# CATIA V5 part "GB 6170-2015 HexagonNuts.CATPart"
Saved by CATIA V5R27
Part number: GB 6170-2015 1型六角螺母
Bounding box of the stored display mesh (mm): x -1.848 to 1.848, y -1.6 to 1.6, z 0 to 1.3
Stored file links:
  E:\资料\Catia超级副本\GB 6170-2015 1型六角螺母\GB 6170-2015 HexagonNuts.CATPart
  E:\资料\Catia超级副本\GB 6170-2015 1型六角螺母\DesignTable1.xlsx
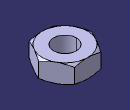
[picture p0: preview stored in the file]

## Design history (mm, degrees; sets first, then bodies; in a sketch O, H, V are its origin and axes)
Parameters
  s = 3.2 mm {design table}
  m = 1.3 mm {design table}
  `公称直径D` = 1.6 mm {design table}
AxisSystem1: origin (0, 0, 0), X (1, 0, 0), Y (0, 1, 0), Z (0, 0, 1)
Set1 "Inputs"
  Plane1: type Normal, Curve Line1, RefPoint Point1, Ratio 0
  Point1: (0, 0, 0), in AxisSystem1
Body1 (main body)
  Sketch1 on Plane1, origin (0, 0, 0), H (1, 0, 0), V (0, 1, 0)
    point P1 (0, 1.6)
    construction circle A1 centre (0, 0) radius 1.8475
    construction circle A2 centre (0, 0) radius 1.6
    point P2 (0.9238, 1.6)
    point P3 (-0.9238, 1.6)
    point P4 (-1.8475, 0)
    point P5 (-0.9238, -1.6)
    point P6 (0.9238, -1.6)
    point P7 (1.8475, 0)
    line L1 (0.9238, 1.6) -> (-0.9238, 1.6)
    line L2 (-0.9238, 1.6) -> (-1.8475, 0)
    line L3 (-1.8475, 0) -> (-0.9238, -1.6)
    line L4 (-0.9238, -1.6) -> (0.9238, -1.6)
    line L5 (0.9238, -1.6) -> (1.8475, 0)
    line L6 (1.8475, 0) -> (0.9238, 1.6)
    construction line L7 (0, 0) -> (0, 1.6)
    circle A3 centre (0, 0) radius 0.8
    radius A3 = 0.8 {= `公称直径D` /2}
    distance L1 L4 = 3.2 {= s}
    coincidence: A1 P2, A1 P3, A1 P4, A1 P5, A1 P6, A1 P7
    tangency: A2 L1, A2 L2, A2 L3, A2 L4, A2 L5, A2 L6
    midpoint: P1 L1
    vertical: L7 V
  Pad1: profile Sketch1, direction (0, 0, 1), length 1.3 {= m}
  Set2
    Line1: type PtDir, RefPoint Point1, Direction (0, 0, 1), Start 0, End 20
    Sketch2 on Plane2, origin (0, 0, 0), H (0, 1, 0), V (0, 0, 1)
      line L1 (-1.6, 1.3) -> (-2.3794, 0.85)
      point P1 (-1.6, 1.3)
      point P2 (-2.3794, 0.85)
      reference intersected line E1 through (0, 1.3) direction (-1, 0) from end face of Pad1
      line L2 (-1.6, 1.3) -> (-2.3794, 1.3)
      point P3 (-2.3794, 1.3)
      line L3 (-2.3794, 1.3) -> (-2.3794, 0.85)
      reference intersected line E2 through (0, 1.3) direction (-1, 0) from end face of Pad1
      reference intersected line E3 (-1.6, 0) -> (-1.6, 1.3) from face of Pad1 from Sketch1.L4
      construction line L4 (1.8007, 0.65) -> (-1.9077, 0.65)
      reference projected line E4 (0, 1.3) -> (-1.6, 1.3) from edge [face of Pad1 from Sketch1.L3 | end face of Pad1]
      reference projected line E5 (0, 0) -> (-1.6, 0) from edge [start face of Pad1 | face of Pad1 from Sketch1.L3]
      point P6 (-2.3794, 0)
      point P7 (-1.6, 0)
      line L5 (-1.6, 0) -> (-2.3794, 0)
      point P8 (-2.3794, 0.45)
      line L6 (-1.6, 0) -> (-2.3794, 0.45)
      line L7 (-2.3794, 0) -> (-2.3794, 0.45)
      angle L1 E1 = 30
      length L3 = 0.45 {= m /2-0.2mm}
      horizontal: L2 H, L4 H
      vertical: L3 V
      coincidence: L2 E2, P1 E3
      symmetry: E4 E5 L4, P3 P6 L4, P1 P7 L4, L2 L5 L4, P2 P8 L4, L1 L6 L4, L3 L7 L4
    Line2: type PtDir, RefPoint Point1, Direction (0, 1, 0), Start 0, End 20
    Plane2: type 2Lines, Element1 Line1, Element2 Line2
  Groove1: profile Sketch2, axis axis of face of Pad1 from Sketch1.A3, angle 360
Relations
  design table, configuration 1, drives s, m, `公称直径D`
